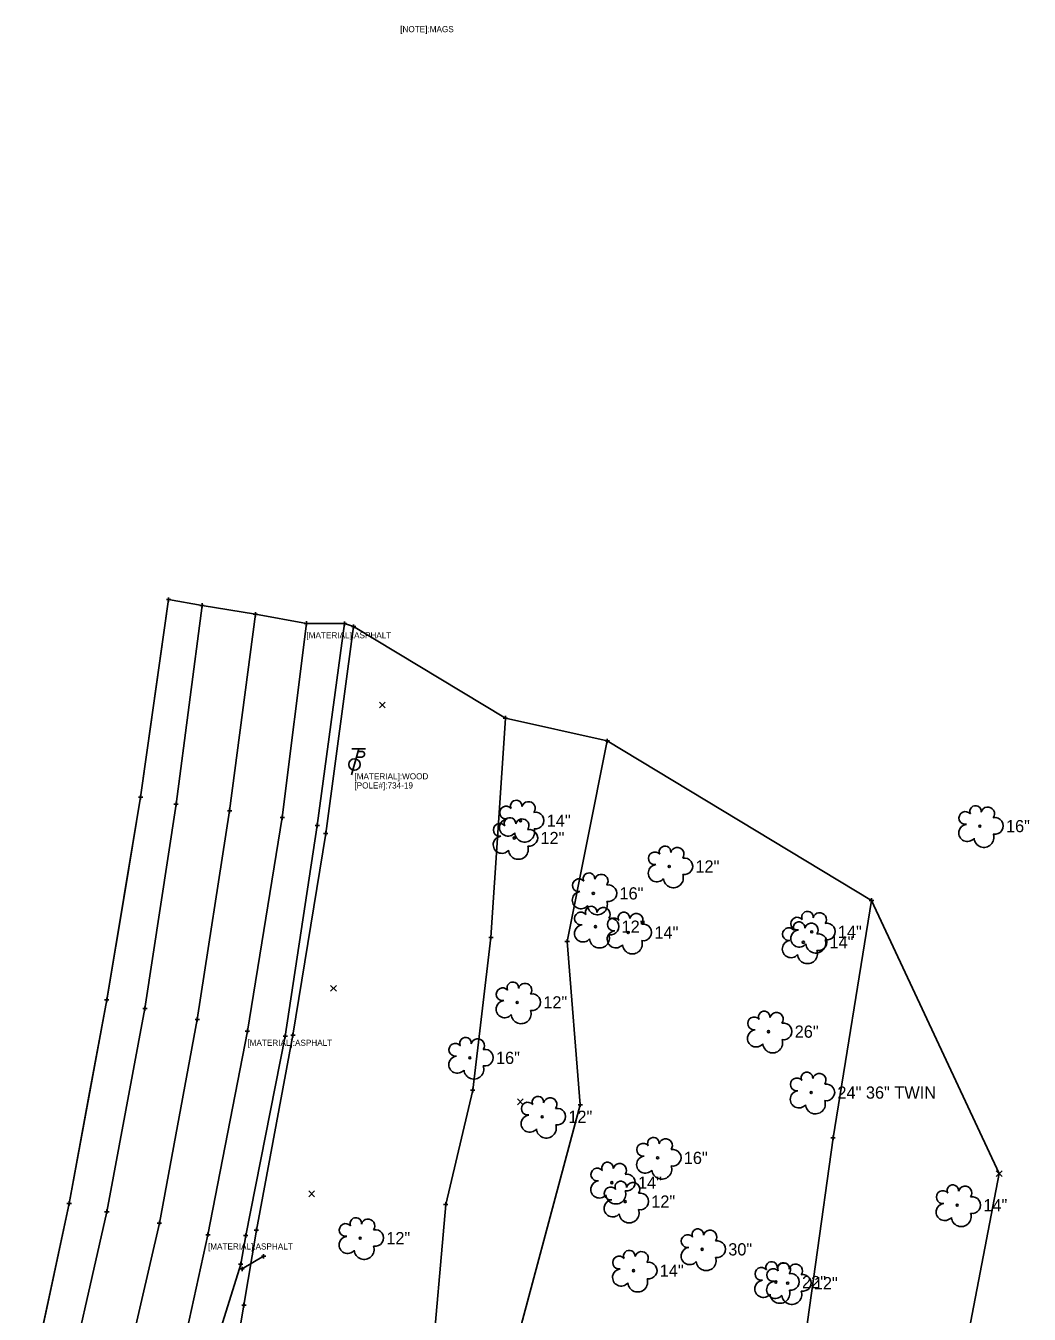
# Model space of a CAD drawing. Extents: x 1380627 to 1381920, y 503402 to 506786.
# Drawn here: x 1381689.4 to 1381919.6, y 504806.3 to 505101.8 of the extents above; entities that cross this region are included whole.
import ezdxf

# ---------------------------------------------------------------- set-up
doc = ezdxf.new("R2010")
doc.units = 0
for name, color, linetype in [('PV_X_COP', 7, 'Continuous'), ('PV_X_EOP', 7, 'Continuous'), ('PV_X_Shoulder', 7, 'Continuous'), ('RD_X_GR_Rt', 7, 'Continuous'), ('SV_X_Control_Cells_Found_Text', 7, 'Continuous'), ('SV_X_Edge_of_Slip', 7, 'Continuous'), ('SV_X_Random_Point', 7, 'Continuous'), ('SV_X_Shot_Marker', 7, 'Continuous'), ('SV_X_Terrain_Boundary', 7, 'Continuous'), ('SV_X_Text', 7, 'Continuous'), ('SV_X_Toe_of_Slope', 7, 'Continuous'), ('SV_X_Top_of_Bank', 7, 'Continuous'), ('UT_X_Misc_Cells', 7, 'Continuous'), ('VG_X_Cells', 7, 'Continuous'), ('VG_X_Text', 7, 'Continuous')]:
    doc.layers.add(name, color=color, linetype=linetype)

msp = doc.modelspace()

# ---------------------------------------------------------------- linework, layer by layer
at = {"layer": 'PV_X_COP'}
msp.add_lwpolyline([(1381709.34, 504780.86), (1381720.03, 504827.18), (1381728.71, 504873.89), (1381736.14, 504921.73), (1381742.06, 504966.83)], dxfattribs=at)
at = {"layer": 'PV_X_EOP'}
for points in [[(1381697.52, 504783.57), (1381707.98, 504829.78), (1381716.73, 504876.36), (1381723.85, 504923.29), (1381729.83, 504968.85)], [(1381720.97, 504778), (1381731.18, 504824.5), (1381740.22, 504871.22), (1381748.22, 504920.18), (1381753.77, 504964.71)]]:
    msp.add_lwpolyline(points, dxfattribs=at)
at = {"layer": 'PV_X_Shoulder'}
for points in [[(1381689.39, 504785.35), (1381699.34, 504831.67), (1381707.97, 504878.35), (1381715.72, 504924.85), (1381722.16, 504970.19)], [(1381715.23, 504719.48), (1381717.19, 504727.23), (1381715.79, 504728.72), (1381721.76, 504752.5), (1381726.9, 504776.21), (1381732.66, 504798.37), (1381738.71, 504817.75), (1381739.85, 504824.31), (1381748.9, 504870.03), (1381756.24, 504918.38), (1381762.48, 504964.69)]]:
    msp.add_lwpolyline(points, dxfattribs=at)
at = {"layer": 'RD_X_GR_Rt'}
msp.add_lwpolyline([(1381719.91, 504724.54), (1381724.94, 504740.97), (1381730.61, 504763.69), (1381735.7, 504786.53), (1381739.43, 504808.33), (1381742.29, 504825.57), (1381750.67, 504870.25), (1381758.18, 504916.55), (1381764.57, 504963.98)], dxfattribs=at)
at = {"layer": 'SV_X_Edge_of_Slip'}
msp.add_lwpolyline([(1381739.02, 504816.63), (1381743.93, 504819.55)], dxfattribs=at)
at = {"layer": 'SV_X_Random_Point'}
for p, q in [((1381770.5, 504945.35), (1381771.83, 504946.69)), ((1381770.5, 504946.69), (1381771.83, 504945.35)), ((1381759.29, 504880.33), (1381760.63, 504881.66)), ((1381759.29, 504881.66), (1381760.63, 504880.33)), ((1381802.17, 504854.29), (1381803.5, 504855.63)), ((1381802.17, 504855.63), (1381803.5, 504854.29)), ((1381911.99, 504837.85), (1381913.32, 504839.18)), ((1381911.99, 504839.18), (1381913.32, 504837.85)), ((1381754.32, 504833.21), (1381755.65, 504834.55)), ((1381754.32, 504834.55), (1381755.65, 504833.21))]:
    msp.add_line(p, q, dxfattribs=at)
at = {"layer": 'SV_X_Shot_Marker'}
for p, q in [((1381721.66, 504970.19), (1381722.66, 504970.19)), ((1381722.16, 504970.69), (1381722.16, 504969.69)), ((1381722.16, 504970.19), (1381722.16, 504970.19)), ((1381729.83, 504969.35), (1381729.83, 504968.35)), ((1381729.33, 504968.85), (1381730.33, 504968.85)), ((1381729.83, 504968.85), (1381729.83, 504968.85)), ((1381741.56, 504966.83), (1381742.56, 504966.83)), ((1381742.06, 504967.33), (1381742.06, 504966.33)), ((1381742.06, 504966.83), (1381742.06, 504966.83)), ((1381753.27, 504964.71), (1381754.27, 504964.71)), ((1381753.77, 504965.21), (1381753.77, 504964.21)), ((1381753.77, 504964.71), (1381753.77, 504964.71)), ((1381761.98, 504964.69), (1381762.98, 504964.69)), ((1381762.48, 504965.19), (1381762.48, 504964.19)), ((1381762.48, 504964.69), (1381762.48, 504964.69)), ((1381764.07, 504963.98), (1381765.07, 504963.98)), ((1381764.57, 504964.48), (1381764.57, 504963.48)), ((1381764.57, 504963.98), (1381764.57, 504963.98)), ((1381798.89, 504943.01), (1381799.89, 504943.01)), ((1381799.39, 504943.51), (1381799.39, 504942.51)), ((1381799.39, 504943.01), (1381799.39, 504943.01)), ((1381822.26, 504937.76), (1381823.26, 504937.76)), ((1381822.76, 504938.26), (1381822.76, 504937.26)), ((1381822.76, 504937.76), (1381822.76, 504937.76)), ((1381715.22, 504924.85), (1381716.22, 504924.85)), ((1381715.72, 504925.35), (1381715.72, 504924.35)), ((1381715.72, 504924.85), (1381715.72, 504924.85)), ((1381723.35, 504923.29), (1381724.35, 504923.29)), ((1381723.85, 504923.79), (1381723.85, 504922.79)), ((1381723.85, 504923.29), (1381723.85, 504923.29)), ((1381735.64, 504921.73), (1381736.64, 504921.73)), ((1381736.14, 504922.23), (1381736.14, 504921.23)), ((1381736.14, 504921.73), (1381736.14, 504921.73)), ((1381747.72, 504920.18), (1381748.72, 504920.18)), ((1381748.22, 504920.68), (1381748.22, 504919.68)), ((1381748.22, 504920.18), (1381748.22, 504920.18)), ((1381756.24, 504918.88), (1381756.24, 504917.88)), ((1381755.74, 504918.38), (1381756.74, 504918.38)), ((1381756.24, 504918.38), (1381756.24, 504918.38)), ((1381757.68, 504916.55), (1381758.68, 504916.55)), ((1381758.18, 504917.05), (1381758.18, 504916.05)), ((1381758.18, 504916.55), (1381758.18, 504916.55)), ((1381882.88, 504901.17), (1381883.88, 504901.17)), ((1381883.38, 504901.67), (1381883.38, 504900.67)), ((1381883.38, 504901.17), (1381883.38, 504901.17)), ((1381795.6, 504892.69), (1381796.6, 504892.69)), ((1381796.1, 504893.19), (1381796.1, 504892.19)), ((1381796.1, 504892.69), (1381796.1, 504892.69)), ((1381813.57, 504892.29), (1381813.57, 504891.29)), ((1381813.07, 504891.79), (1381814.07, 504891.79)), ((1381813.57, 504891.79), (1381813.57, 504891.79)), ((1381707.47, 504878.35), (1381708.47, 504878.35)), ((1381707.97, 504878.85), (1381707.97, 504877.85)), ((1381707.97, 504878.35), (1381707.97, 504878.35)), ((1381716.23, 504876.36), (1381717.23, 504876.36)), ((1381716.73, 504876.86), (1381716.73, 504875.86)), ((1381716.73, 504876.36), (1381716.73, 504876.36)), ((1381728.71, 504874.39), (1381728.71, 504873.39)), ((1381728.21, 504873.89), (1381729.21, 504873.89)), ((1381728.71, 504873.89), (1381728.71, 504873.89)), ((1381740.22, 504871.72), (1381740.22, 504870.72)), ((1381739.72, 504871.22), (1381740.72, 504871.22)), ((1381740.22, 504871.22), (1381740.22, 504871.22)), ((1381748.4, 504870.03), (1381749.4, 504870.03)), ((1381748.9, 504870.53), (1381748.9, 504869.53)), ((1381748.9, 504870.03), (1381748.9, 504870.03)), ((1381750.17, 504870.25), (1381751.17, 504870.25)), ((1381750.67, 504870.75), (1381750.67, 504869.75)), ((1381750.67, 504870.25), (1381750.67, 504870.25)), ((1381791.43, 504857.65), (1381792.43, 504857.65)), ((1381791.93, 504858.15), (1381791.93, 504857.15)), ((1381791.93, 504857.65), (1381791.93, 504857.65)), ((1381816.09, 504854.3), (1381817.09, 504854.3)), ((1381816.59, 504854.8), (1381816.59, 504853.8)), ((1381816.59, 504854.3), (1381816.59, 504854.3)), ((1381874.06, 504846.72), (1381875.06, 504846.72)), ((1381874.56, 504847.22), (1381874.56, 504846.22)), ((1381874.56, 504846.72), (1381874.56, 504846.72)), ((1381698.84, 504831.67), (1381699.84, 504831.67)), ((1381699.34, 504832.17), (1381699.34, 504831.17)), ((1381699.34, 504831.67), (1381699.34, 504831.67)), ((1381707.98, 504830.28), (1381707.98, 504829.28)), ((1381785.23, 504831.46), (1381786.23, 504831.46)), ((1381785.73, 504831.96), (1381785.73, 504830.96)), ((1381785.73, 504831.46), (1381785.73, 504831.46)), ((1381707.48, 504829.78), (1381708.48, 504829.78)), ((1381707.98, 504829.78), (1381707.98, 504829.78)), ((1381719.53, 504827.18), (1381720.53, 504827.18)), ((1381720.03, 504827.68), (1381720.03, 504826.68)), ((1381720.03, 504827.18), (1381720.03, 504827.18)), ((1381730.68, 504824.5), (1381731.68, 504824.5)), ((1381731.18, 504825), (1381731.18, 504824)), ((1381731.18, 504824.5), (1381731.18, 504824.5)), ((1381739.35, 504824.31), (1381740.35, 504824.31)), ((1381739.85, 504824.81), (1381739.85, 504823.81)), ((1381739.85, 504824.31), (1381739.85, 504824.31)), ((1381741.79, 504825.57), (1381742.79, 504825.57)), ((1381742.29, 504826.07), (1381742.29, 504825.07)), ((1381742.29, 504825.57), (1381742.29, 504825.57)), ((1381738.71, 504818.25), (1381738.71, 504817.25)), ((1381743.43, 504819.55), (1381744.43, 504819.55)), ((1381743.93, 504820.05), (1381743.93, 504819.05)), ((1381743.93, 504819.55), (1381743.93, 504819.55)), ((1381738.21, 504817.75), (1381739.21, 504817.75)), ((1381738.52, 504816.63), (1381739.52, 504816.63)), ((1381738.71, 504817.75), (1381738.71, 504817.75)), ((1381739.02, 504817.13), (1381739.02, 504816.13)), ((1381739.02, 504816.63), (1381739.02, 504816.63)), ((1381738.93, 504808.33), (1381739.93, 504808.33)), ((1381739.43, 504808.83), (1381739.43, 504807.83)), ((1381739.43, 504808.33), (1381739.43, 504808.33))]:
    msp.add_line(p, q, dxfattribs=at)
at = {"layer": 'SV_X_Terrain_Boundary'}
msp.add_lwpolyline([(1381902.08, 504783.53), (1381912.66, 504838.51), (1381883.38, 504901.17), (1381822.76, 504937.76), (1381799.39, 504943.01), (1381764.57, 504963.98), (1381762.48, 504964.69), (1381753.77, 504964.71), (1381742.06, 504966.83), (1381729.83, 504968.85), (1381722.16, 504970.19), (1381719.24, 504949.6), (1381715.72, 504924.85), (1381712.08, 504903), (1381707.97, 504878.35), (1381703.89, 504856.25), (1381699.34, 504831.67), (1381694.64, 504809.79), (1381689.39, 504785.35)], dxfattribs=at)
at = {"layer": 'SV_X_Toe_of_Slope'}
for points in [[(1381764.57, 504704.36), (1381777.55, 504716.02), (1381774.07, 504742.51), (1381782.28, 504792.24), (1381785.73, 504831.46), (1381791.93, 504857.65), (1381796.1, 504892.69), (1381799.39, 504943.01)], [(1381809.7, 504557.46), (1381827.24, 504600.65), (1381846.42, 504650.4), (1381850.64, 504694.87), (1381860.29, 504748.65), (1381866.47, 504788.59), (1381874.56, 504846.72), (1381883.38, 504901.17)]]:
    msp.add_lwpolyline(points, dxfattribs=at)
at = {"layer": 'SV_X_Top_of_Bank'}
msp.add_lwpolyline([(1381767.38, 504703.3), (1381779.81, 504699.36), (1381788.94, 504713.32), (1381796.76, 504747.32), (1381798.75, 504787.76), (1381816.59, 504854.3), (1381813.57, 504891.79), (1381822.76, 504937.76)], dxfattribs=at)
at = {"layer": 'UT_X_Misc_Cells'}
for p, q in [((1381765.75, 504935.95), (1381764.14, 504929.95)), ((1381767.35, 504935.95), (1381764.15, 504935.95)), ((1381765.24, 504934.07), (1381766.44, 504934.07)), ((1381765.59, 504935.35), (1381766.44, 504935.35))]:
    msp.add_line(p, q, dxfattribs=at)
msp.add_circle((1381764.78, 504932.35), 1.3, dxfattribs=at)
msp.add_arc((1381766.45, 504934.71), 0.638, 268.8767, 91.1233, dxfattribs=at)
at = {"layer": 'VG_X_Cells'}
for centre in [(1381802.88, 504919.46), (1381801.44, 504915.49), (1381908.22, 504918.22), (1381836.99, 504908.96), (1381819.57, 504902.79), (1381820.05, 504895.16), (1381827.58, 504893.8), (1381869.67, 504893.98), (1381867.75, 504891.56), (1381802.09, 504877.78), (1381859.76, 504871.08), (1381791.24, 504865.07), (1381869.56, 504857.1), (1381807.84, 504851.54), (1381834.32, 504842.12), (1381823.81, 504836.43), (1381826.86, 504832.09), (1381903.03, 504831.25), (1381766.08, 504823.71), (1381844.52, 504821.14), (1381828.8, 504816.24), (1381861.44, 504813.64), (1381864.15, 504813.39)]:
    msp.add_circle(centre, 0.24, dxfattribs=at)
for centre, radius, start, end in [((1381799.57, 504921.32), 1.47, 39.0625, 279.5412), ((1381801.89, 504922.83), 1.32, 354.0047, 205.9741), ((1381804.7, 504922.29), 1.55, 323.83, 165.0376), ((1381907.24, 504921.59), 1.32, 354.0047, 205.9741), ((1381910.05, 504921.05), 1.55, 323.83, 165.0376), ((1381798.13, 504917.35), 1.47, 39.0625, 279.5412), ((1381800.02, 504917.91), 1.97, 96.1722, 320.5737), ((1381800.45, 504918.85), 1.32, 354.0047, 205.9741), ((1381803.26, 504918.32), 1.55, 323.83, 165.0376), ((1381806.34, 504919.5), 1.91, 259.1453, 101.4596), ((1381904.91, 504920.09), 1.47, 39.0625, 279.5412), ((1381911.68, 504918.26), 1.91, 259.1453, 101.4596), ((1381798.58, 504913.94), 1.97, 96.1722, 320.5737), ((1381803.82, 504916.85), 2.28, 184.9476, 19.4572), ((1381804.9, 504915.52), 1.91, 259.1453, 101.4596), ((1381905.37, 504916.67), 1.97, 96.1722, 320.5737), ((1381909.17, 504915.62), 2.28, 184.9476, 19.4572), ((1381802.38, 504912.88), 2.28, 184.9476, 19.4572), ((1381836.01, 504912.33), 1.32, 354.0047, 205.9741), ((1381838.82, 504911.79), 1.55, 323.83, 165.0376), ((1381833.68, 504910.83), 1.47, 39.0625, 279.5412), ((1381840.45, 504909), 1.91, 259.1453, 101.4596), ((1381818.58, 504906.16), 1.32, 354.0047, 205.9741), ((1381821.39, 504905.62), 1.55, 323.83, 165.0376), ((1381834.14, 504907.42), 1.97, 96.1722, 320.5737), ((1381837.94, 504906.36), 2.28, 184.9476, 19.4572), ((1381816.26, 504904.65), 1.47, 39.0625, 279.5412), ((1381823.03, 504902.83), 1.91, 259.1453, 101.4596), ((1381816.71, 504901.24), 1.97, 96.1722, 320.5737), ((1381816.74, 504897.02), 1.47, 39.0625, 279.5412), ((1381819.07, 504898.52), 1.32, 354.0047, 205.9741), ((1381820.51, 504900.18), 2.28, 184.9476, 19.4572), ((1381821.88, 504897.99), 1.55, 323.83, 165.0376), ((1381826.6, 504897.17), 1.32, 354.0047, 205.9741), ((1381829.41, 504896.63), 1.55, 323.83, 165.0376), ((1381868.69, 504897.35), 1.32, 354.0047, 205.9741), ((1381871.5, 504896.81), 1.55, 323.83, 165.0376), ((1381817.2, 504893.61), 1.97, 96.1722, 320.5737), ((1381824.27, 504895.66), 1.47, 39.0625, 279.5412), ((1381823.51, 504895.19), 1.91, 259.1453, 101.4596), ((1381831.04, 504893.84), 1.91, 259.1453, 101.4596), ((1381866.36, 504895.85), 1.47, 39.0625, 279.5412), ((1381866.76, 504894.93), 1.32, 354.0047, 205.9741), ((1381869.57, 504894.39), 1.55, 323.83, 165.0376), ((1381873.13, 504894.02), 1.91, 259.1453, 101.4596), ((1381821, 504892.55), 2.28, 184.9476, 19.4572), ((1381824.73, 504892.25), 1.97, 96.1722, 320.5737), ((1381864.44, 504893.42), 1.47, 39.0625, 279.5412), ((1381866.82, 504892.44), 1.97, 96.1722, 320.5737), ((1381870.62, 504891.38), 2.28, 184.9476, 19.4572), ((1381871.21, 504891.59), 1.91, 259.1453, 101.4596), ((1381828.53, 504891.19), 2.28, 184.9476, 19.4572), ((1381864.89, 504890.01), 1.97, 96.1722, 320.5737), ((1381868.69, 504888.95), 2.28, 184.9476, 19.4572), ((1381798.78, 504879.65), 1.47, 39.0625, 279.5412), ((1381801.1, 504881.15), 1.32, 354.0047, 205.9741), ((1381803.91, 504880.61), 1.55, 323.83, 165.0376), ((1381799.23, 504876.24), 1.97, 96.1722, 320.5737), ((1381805.55, 504877.82), 1.91, 259.1453, 101.4596), ((1381803.03, 504875.18), 2.28, 184.9476, 19.4572), ((1381856.45, 504872.95), 1.47, 39.0625, 279.5412), ((1381858.78, 504874.45), 1.32, 354.0047, 205.9741), ((1381861.59, 504873.91), 1.55, 323.83, 165.0376), ((1381856.91, 504869.53), 1.97, 96.1722, 320.5737), ((1381863.22, 504871.12), 1.91, 259.1453, 101.4596), ((1381790.25, 504868.44), 1.32, 354.0047, 205.9741), ((1381793.06, 504867.9), 1.55, 323.83, 165.0376), ((1381860.71, 504868.48), 2.28, 184.9476, 19.4572), ((1381788.38, 504863.52), 1.97, 96.1722, 320.5737), ((1381787.93, 504866.93), 1.47, 39.0625, 279.5412), ((1381794.7, 504865.1), 1.91, 259.1453, 101.4596), ((1381792.18, 504862.46), 2.28, 184.9476, 19.4572), ((1381866.25, 504858.96), 1.47, 39.0625, 279.5412), ((1381868.58, 504860.47), 1.32, 354.0047, 205.9741), ((1381871.39, 504859.93), 1.55, 323.83, 165.0376), ((1381866.71, 504855.55), 1.97, 96.1722, 320.5737), ((1381873.02, 504857.14), 1.91, 259.1453, 101.4596), ((1381804.53, 504853.41), 1.47, 39.0625, 279.5412), ((1381806.86, 504854.91), 1.32, 354.0047, 205.9741), ((1381809.67, 504854.37), 1.55, 323.83, 165.0376), ((1381870.51, 504854.49), 2.28, 184.9476, 19.4572), ((1381804.99, 504849.99), 1.97, 96.1722, 320.5737), ((1381811.3, 504851.58), 1.91, 259.1453, 101.4596), ((1381808.79, 504848.94), 2.28, 184.9476, 19.4572), ((1381831.01, 504843.98), 1.47, 39.0625, 279.5412), ((1381833.34, 504845.49), 1.32, 354.0047, 205.9741), ((1381836.15, 504844.95), 1.55, 323.83, 165.0376), ((1381831.47, 504840.57), 1.97, 96.1722, 320.5737), ((1381837.78, 504842.15), 1.91, 259.1453, 101.4596), ((1381820.5, 504838.3), 1.47, 39.0625, 279.5412), ((1381822.82, 504839.8), 1.32, 354.0047, 205.9741), ((1381825.63, 504839.26), 1.55, 323.83, 165.0376), ((1381835.27, 504839.51), 2.28, 184.9476, 19.4572), ((1381820.95, 504834.88), 1.97, 96.1722, 320.5737), ((1381825.87, 504835.46), 1.32, 354.0047, 205.9741), ((1381827.27, 504836.47), 1.91, 259.1453, 101.4596), ((1381828.68, 504834.92), 1.55, 323.83, 165.0376), ((1381902.04, 504834.62), 1.32, 354.0047, 205.9741), ((1381823.55, 504833.95), 1.47, 39.0625, 279.5412), ((1381824.75, 504833.83), 2.28, 184.9476, 19.4572), ((1381830.32, 504832.13), 1.91, 259.1453, 101.4596), ((1381899.72, 504833.11), 1.47, 39.0625, 279.5412), ((1381904.85, 504834.08), 1.55, 323.83, 165.0376), ((1381906.49, 504831.28), 1.91, 259.1453, 101.4596), ((1381824, 504830.54), 1.97, 96.1722, 320.5737), ((1381827.8, 504829.48), 2.28, 184.9476, 19.4572), ((1381900.17, 504829.7), 1.97, 96.1722, 320.5737), ((1381765.09, 504827.08), 1.32, 354.0047, 205.9741), ((1381767.9, 504826.54), 1.55, 323.83, 165.0376), ((1381903.97, 504828.64), 2.28, 184.9476, 19.4572), ((1381763.22, 504822.16), 1.97, 96.1722, 320.5737), ((1381762.77, 504825.58), 1.47, 39.0625, 279.5412), ((1381769.54, 504823.75), 1.91, 259.1453, 101.4596), ((1381841.21, 504823.01), 1.47, 39.0625, 279.5412), ((1381843.53, 504824.51), 1.32, 354.0047, 205.9741), ((1381846.34, 504823.97), 1.55, 323.83, 165.0376), ((1381767.02, 504821.11), 2.28, 184.9476, 19.4572), ((1381841.66, 504819.59), 1.97, 96.1722, 320.5737), ((1381847.98, 504821.18), 1.91, 259.1453, 101.4596), ((1381825.5, 504818.1), 1.47, 39.0625, 279.5412), ((1381827.82, 504819.6), 1.32, 354.0047, 205.9741), ((1381830.63, 504819.07), 1.55, 323.83, 165.0376), ((1381845.46, 504818.54), 2.28, 184.9476, 19.4572), ((1381860.45, 504817), 1.32, 354.0047, 205.9741), ((1381825.95, 504814.69), 1.97, 96.1722, 320.5737), ((1381832.27, 504816.27), 1.91, 259.1453, 101.4596), ((1381858.13, 504815.5), 1.47, 39.0625, 279.5412), ((1381860.84, 504815.25), 1.47, 39.0625, 279.5412), ((1381863.26, 504816.46), 1.55, 323.83, 165.0376), ((1381863.17, 504816.76), 1.32, 354.0047, 205.9741), ((1381865.98, 504816.22), 1.55, 323.83, 165.0376), ((1381864.9, 504813.67), 1.91, 259.1453, 101.4596), ((1381867.61, 504813.43), 1.91, 259.1453, 101.4596), ((1381829.75, 504813.63), 2.28, 184.9476, 19.4572), ((1381858.58, 504812.09), 1.97, 96.1722, 320.5737), ((1381861.3, 504811.84), 1.97, 96.1722, 320.5737), ((1381862.38, 504811.03), 2.28, 184.9476, 19.4572), ((1381865.1, 504810.78), 2.28, 184.9476, 19.4572)]:
    msp.add_arc(centre, radius, start, end, dxfattribs=at)

# ---------------------------------------------------------------- texts
at = {"layer": 'SV_X_Control_Cells_Found_Text'}
msp.add_text('[NOTE]:MAGS', height=1.4, dxfattribs=at).set_placement((1381775.28, 505100.34))
at = {"layer": 'SV_X_Text'}
for s, p in [('[MATERIAL]:ASPHALT', (1381753.77, 504961.31)), ('[MATERIAL]:WOOD', (1381764.78, 504928.95)), ('[POLE#]:734-19', (1381764.78, 504926.85)), ('[MATERIAL]:ASPHALT', (1381740.22, 504867.82)), ('[MATERIAL]:ASPHALT', (1381731.18, 504821.1))]:
    msp.add_text(s, height=1.4, dxfattribs=at).set_placement(p)
at = {"layer": 'VG_X_Text'}
for s, p in [('14"', (1381808.88, 504918.06)), ('16"', (1381914.22, 504916.82)), ('12"', (1381807.44, 504914.09)), ('12"', (1381842.99, 504907.57)), ('16"', (1381825.57, 504901.39)), ('12"', (1381826.05, 504893.76)), ('14"', (1381833.58, 504892.4)), ('14"', (1381875.67, 504892.58)), ('14"', (1381873.75, 504890.16)), ('12"', (1381808.09, 504876.39)), ('26"', (1381865.76, 504869.68)), ('16"', (1381797.24, 504863.67)), ('24" 36" TWIN', (1381875.56, 504855.7)), ('12"', (1381813.84, 504850.14)), ('16"', (1381840.32, 504840.72)), ('14"', (1381829.81, 504835.03)), ('12"', (1381832.86, 504830.69)), ('14"', (1381909.03, 504829.85)), ('12"', (1381772.08, 504822.31)), ('30"', (1381850.52, 504819.74)), ('14"', (1381834.8, 504814.84)), ('22"', (1381867.44, 504812.23)), ('12"', (1381870.15, 504811.99))]:
    msp.add_text(s, height=2.8, dxfattribs=at).set_placement(p)

doc.saveas('drawing.dxf')
